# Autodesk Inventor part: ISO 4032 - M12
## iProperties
Author: Tobben
Created: 2001-12
Part Number: ISO 4032 - M12
Catalog Web Link: file:///F:/Cad/Autodesk/Inventor 5/Content/Iso/index.htm?doNavigateId=81B6DECA-D49F-45EF-94B6-61B88B49772D|F0100A5F59104064B8BFC37D67EBD9B|true
Description: Hex Nut
Document SubType Name: Standard Catalog Part
Standard: ISO 4032 - M12
Designer: Tobben
CLASSIFICATION: 31161727 un/spsc
MANUFACTURER: ISO Standard System
Control State: 0
Master: False
Checked Out: False
PropertySet Name: Design Tracking Control
Shininess: 64.0
Angle Display Precision: 2
Document Length Units: 11269
Document Angle Units: 11283
Document Time Units: 11279
Document Mass Units: 11290
Document Length Units Precision: 3
Document Angle Units Precision: 2
Compacted: True
PropertySet Name: _Private Model Information
Density: 0.0
Volumn: 0.0
Area: 0.0
PropertySet Name: Model Information
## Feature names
1. Base1
